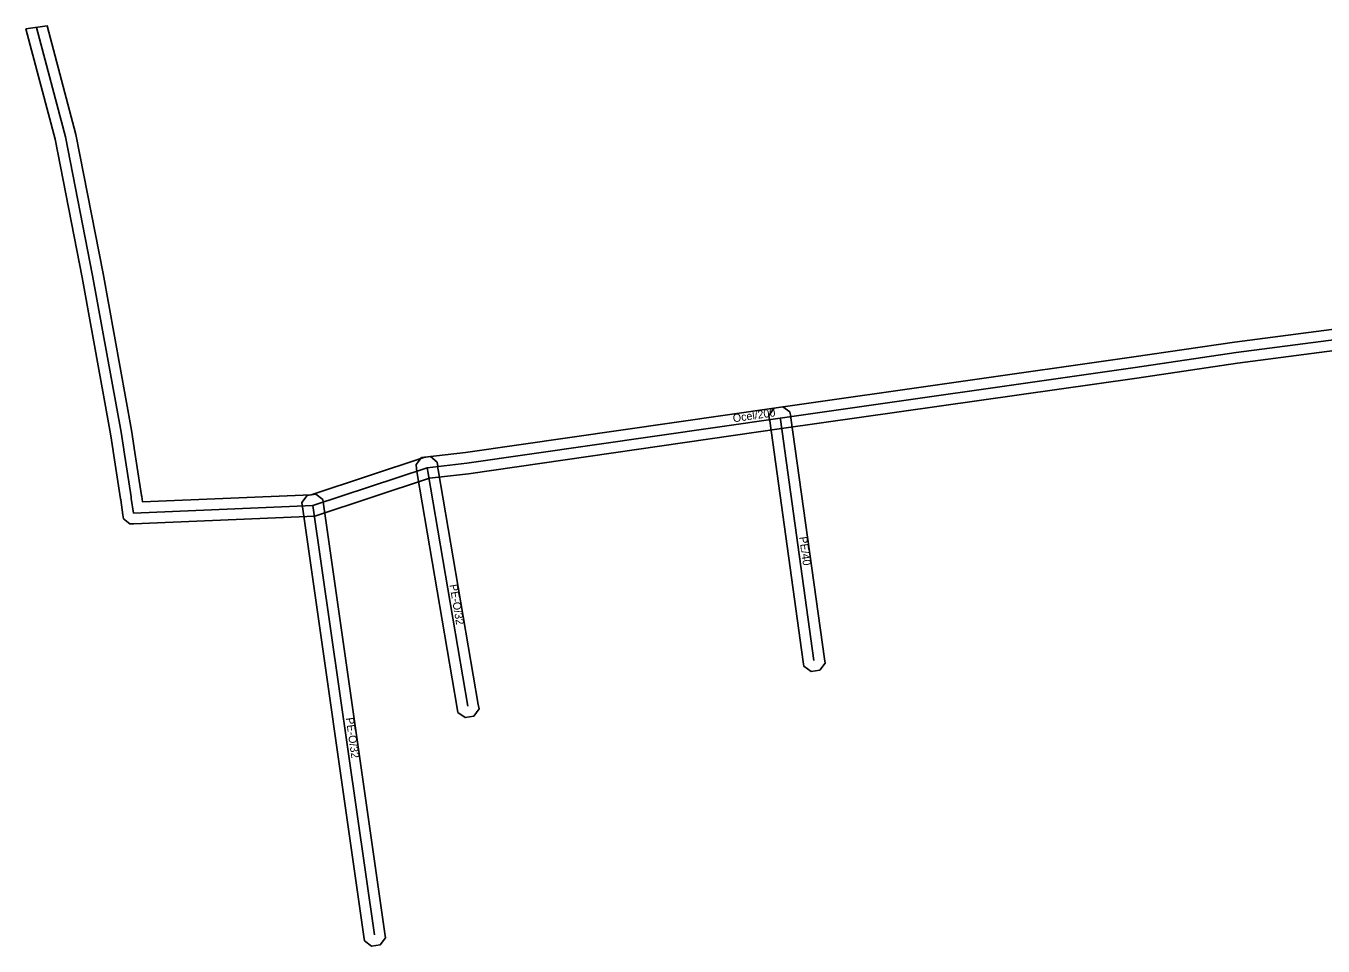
# Model space of a CAD drawing. Extents: x -866668 to -866425, y -1041329 to -1040263.
# Drawn here: x -866667.7 to -866546.2, y -1040349.3 to -1040263.1 of the extents above; entities that cross this region are included whole.
import ezdxf

# ---------------------------------------------------------------- set-up
doc = ezdxf.new("R2010")
doc.units = 0
for name, color, linetype in [('1', 7, 'Continuous'), ('24', 7, 'Continuous'), ('30', 7, 'Continuous')]:
    doc.layers.add(name, color=color, linetype=linetype)

msp = doc.modelspace()

# ---------------------------------------------------------------- linework, layer by layer
at = {"layer": '1'}
msp.add_lwpolyline([(-866507.8, -1040288.64), (-866554.18, -1040294.69), (-866563.61, -1040296.08), (-866596.89, -1040300.82), (-866626.24, -1040305.05), (-866629.89, -1040305.46), (-866640.62, -1040309.01), (-866657.57, -1040309.73), (-866657.95, -1040309.74), (-866658.54, -1040309.26), (-866658.6, -1040308.88), (-866658.81, -1040307.5), (-866658.83, -1040307.38), (-866659.52, -1040302.94), (-866659.52, -1040302.91), (-866659.77, -1040301.31), (-866662.43, -1040286.67), (-866664.96, -1040273.7), (-866667.69, -1040263.38), (-866665.7, -1040263.1), (-866663.02, -1040273.26), (-866660.47, -1040286.3), (-866657.79, -1040300.97), (-866657.54, -1040302.62), (-866657.54, -1040302.64), (-866656.85, -1040307.07), (-866656.83, -1040307.19), (-866656.76, -1040307.69), (-866640.98, -1040307.03), (-866630.32, -1040303.5), (-866626.5, -1040303.07), (-866597.17, -1040298.84), (-866563.9, -1040294.1), (-866554.46, -1040292.71), (-866508.06, -1040286.66)], dxfattribs=at)
for points in [[(-866596.11, -1040299.26), (-866596.04, -1040299.67), (-866596.02, -1040299.8), (-866592.88, -1040322.39), (-866592.82, -1040322.8), (-866593.32, -1040323.46), (-866593.73, -1040323.52), (-866594.14, -1040323.58), (-866594.8, -1040323.08), (-866594.86, -1040322.67), (-866598, -1040300.1), (-866598.02, -1040299.99), (-866598.08, -1040299.59), (-866597.6, -1040298.91), (-866597.19, -1040298.84), (-866596.79, -1040298.78)], [(-866629.15, -1040303.96), (-866629.11, -1040304.37), (-866629.09, -1040304.52), (-866629.06, -1040304.67), (-866625.31, -1040326.66), (-866625.24, -1040327.07), (-866625.72, -1040327.75), (-866626.13, -1040327.82), (-866626.54, -1040327.89), (-866627.22, -1040327.41), (-866627.29, -1040327), (-866631.04, -1040305.01), (-866631.07, -1040304.8), (-866631.09, -1040304.59), (-866631.14, -1040304.18), (-866630.62, -1040303.53), (-866630.21, -1040303.49), (-866629.8, -1040303.44)], [(-866639.87, -1040307.47), (-866639.81, -1040307.88), (-866634.06, -1040348.1), (-866634, -1040348.51), (-866634.5, -1040349.17), (-866634.91, -1040349.23), (-866635.32, -1040349.29), (-866635.98, -1040348.79), (-866636.04, -1040348.38), (-866641.79, -1040308.16), (-866641.85, -1040307.75), (-866641.35, -1040307.09), (-866640.94, -1040307.03), (-866640.53, -1040306.97)]]:
    msp.add_lwpolyline(points, close=True, dxfattribs=at)
at = {"layer": '24'}
for points in [[(-866666.69, -1040263.24), (-866663.99, -1040273.48), (-866661.45, -1040286.48), (-866658.78, -1040301.14), (-866658.53, -1040302.76), (-866658.53, -1040302.79), (-866657.84, -1040307.22), (-866657.82, -1040307.35), (-866657.61, -1040308.73), (-866640.8, -1040308.02), (-866630.1, -1040304.48), (-866626.37, -1040304.06), (-866597.03, -1040299.83), (-866563.76, -1040295.09), (-866554.32, -1040293.7), (-866507.93, -1040287.65), (-866500.11, -1040286.67), (-866498.56, -1040286.48)], [(-866597.03, -1040299.83), (-866597.01, -1040299.95), (-866593.87, -1040322.53)], [(-866630.1, -1040304.48), (-866630.08, -1040304.66), (-866630.05, -1040304.84), (-866626.3, -1040326.83)], [(-866640.8, -1040308.02), (-866635.05, -1040348.24)]]:
    msp.add_lwpolyline(points, dxfattribs=at)

# ---------------------------------------------------------------- texts
at = {"layer": '30'}
for s, rotation, p in [('Ocel/200', 8.2039, (-866601.41, -1040300.23)), ('PE/40', 277.9168, (-866595.25, -1040310.98)), ('PE-O/32', 279.6777, (-866628.01, -1040315.46)), ('PE-O/32', 278.1361, (-866637.73, -1040327.93))]:
    msp.add_text(s, height=0.75, rotation=rotation, dxfattribs=at).set_placement(p)

doc.saveas('drawing.dxf')
